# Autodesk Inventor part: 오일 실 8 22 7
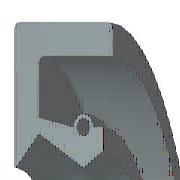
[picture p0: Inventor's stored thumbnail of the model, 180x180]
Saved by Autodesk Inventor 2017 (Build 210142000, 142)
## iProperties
IsCustomPart: 1
Created: 2012-02
Part Number: 오일 실 8 22 7
Material: 고무
Description: 오일-실
Document SubType Name: Modeling
Standard: KS B 2804
Designer: mduedu
Standards Organization: KS
Language: ko-KR
Size Designation: D - 8 22 7
Categories: <MemberInstance><Categories><Category DisplayName="샤프트 부품" InternalName="7f7aeb1f-a693-4053-b835-cee3144e0d98" Mnemonic="SHFT"><Category DisplayName="실링" Intern
Density: 0.93 g/cm^3
Appearance: 고무 - 검은색 - 버전 1.1
Author: mduedu
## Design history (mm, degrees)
revolve "본체" stored, may be unused: angle "d17" = 90 deg
revolve "스프링1" stored, may be unused: angle "d18" = 90 deg
body "Solid1"
sketch "스케치1"
  geometry: L1 (0, 11)-(7, 11); L2 (7, 9.25)-(1.75, 9.25); L3 (1.75, 5.75)-(4.9, 4); L4 (4.9, 4)-(0, 4); L5 (0, 0)-(9.586, 0) reference; L6 (4.9, 4)-(6.3, 4.875); L7 (0, 18)-(0, -3) reference; L8 (-1.941, 0)-(11.507, 0) reference; L9 (4.2, 6.1)-(1.75, 6.59); L10 (1.75, 6.59)-(1.75, 9.25); L11 (0, 11)-(0, 4.088); L12 (4.9, 4)-(0, 4); L13 (1.75, 5.75)-(0.152, 4.028); L14 (7, 11)-(7, 9.25); L15 (5.6, 6.1)-(6.3, 6.1); L16 (6.3, 6.1)-(6.3, 4.875); C1 r 0.455 at (4.9, 6.1); A1 r 0.7 centre (4.9, 6.1) between (5.6, 6.1) and (4.2, 6.1); A2 r 0.088 centre (0.088, 4.088) between (0, 4.088) and (0.152, 4.028); 1 further point
  constraints: 28 end point, 5 horizontal alignment, 5 point on line, 4 point on circle, 4 vertical alignment, 3 centre point, 3 tangent, 2 collinear, 2 horizontal, 2 perpendicular, 1 coincident, 1 parallel
  dimensions: "d0" = 22 diameter of L1 L5 (= SD2); "d1" = 1.75 distance of L1.end L2.start (= SD); "d2" = 0.91 diameter of C1 (= SPDI); "d3" = 1.4 diameter of A1 (= SPDA); "d4" = 8 diameter of L3.end L5 (= NND); "d5" = 11.5 diameter of L3.start L5 (= TKDM); "d7" = 13.18 diameter of L9.end L5 (= TKDM + 0.24 x SWDT); "d8" = 1.75 distance between parallel lines of L11 L10 (= SD); "d9" = 4.9 distance from line of L11 C1.centre (= SPDST); "d10" = 12.2 diameter of C1.centre L5 (= HLDM); "d11" = 0.0875 radius of A2 (= 0.25 x LAB); "d12" = 6.3 distance between parallel lines of L11 L16 (= SDI); "d13" = 9.75 diameter of L6.end L5 (= ABDM); "d14" = 7 distance from line of L11 L1.end (= SWDT)
fillet "모깎기1" dims "d6" = 0.3 (= RR)
other parameters: "SD2" = 22 [user parameter; used in 1 equation term], "SWDT" = 7 [user parameter; used in 2 equation terms], "RR" = 0.3 [user parameter; used in 1 equation term], "SD" = 1.75 [user parameter; used in 2 equation terms], "NND" = 8 [user parameter; used in 1 equation term], "SPDA" = 1.4 [user parameter; used in 1 equation term], "SPDI" = 0.91 [user parameter; used in 1 equation term], "TKDM" = 11.5 [user parameter; used in 2 equation terms], "HLDM" = 12.2 [user parameter; used in 1 equation term], "ABDM" = 9.75 [user parameter; used in 1 equation term], "SDI" = 6.3 [user parameter; used in 1 equation term], "SPDST" = 4.9 [user parameter; used in 1 equation term], "LAB" = 0.35 [user parameter; used in 1 equation term], "d15" = 0, "d16" = 0, "d19" = 0
